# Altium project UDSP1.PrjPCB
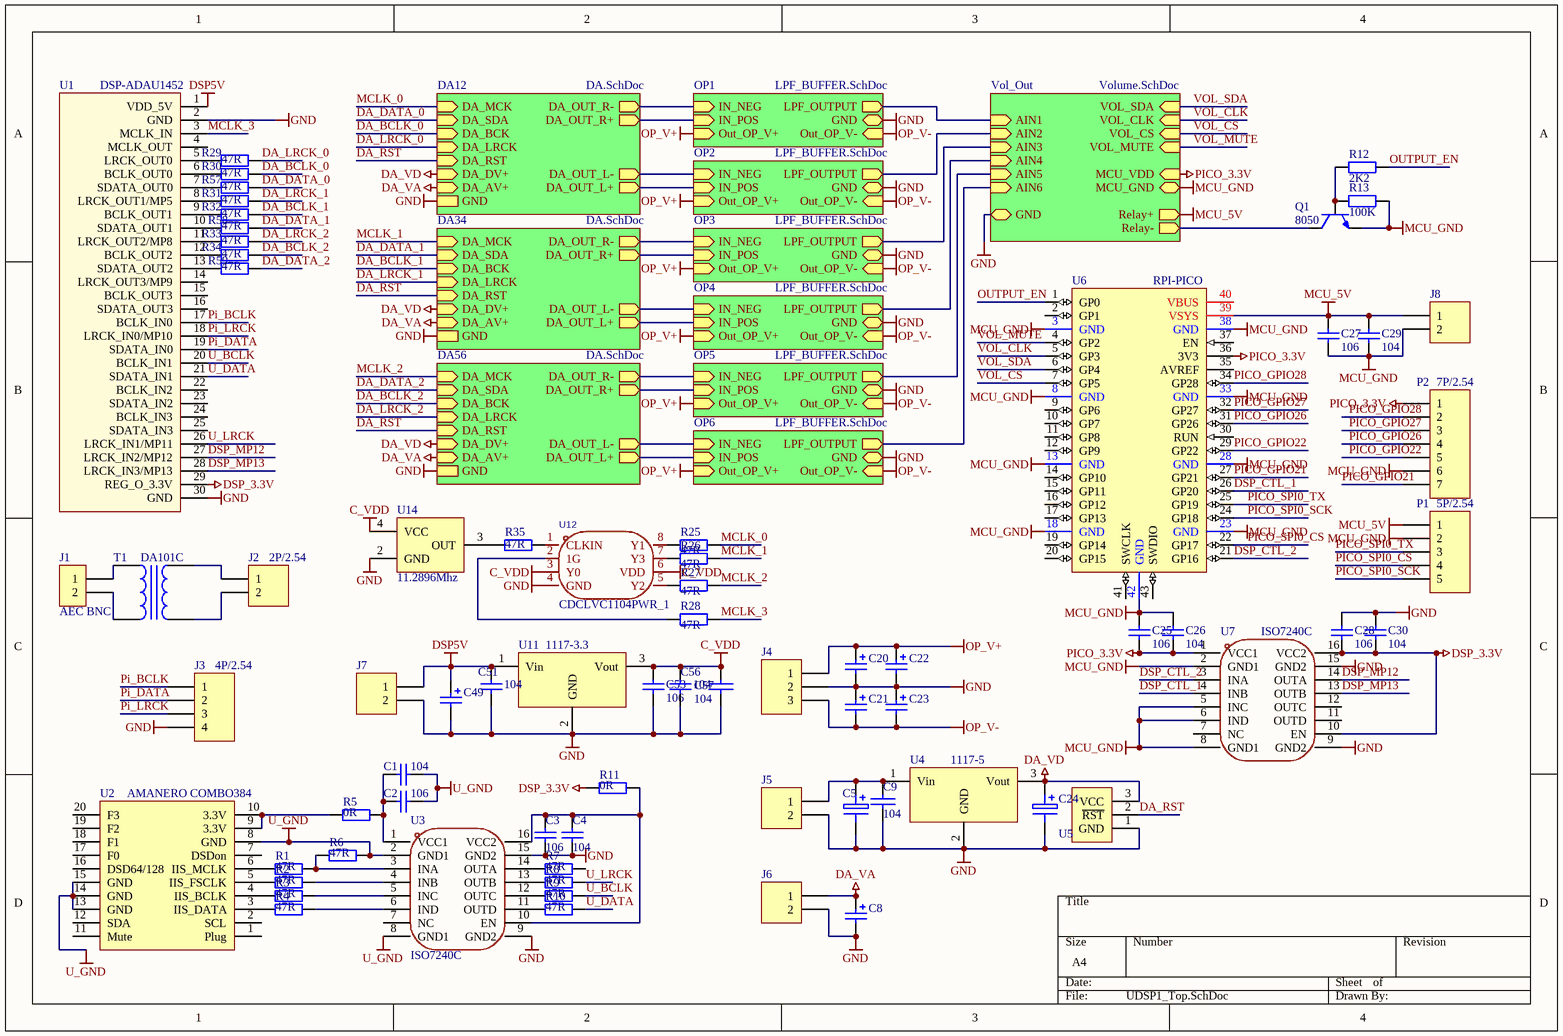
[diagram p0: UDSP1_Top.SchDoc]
4 sheets, 319 parts. Net scope: hierarchical (ports join the sheet entries above them; power ports are global).
Sheets:
  UDSP1_Top.SchDoc
    DA56 = DA.SchDoc
    Vol_Out = Volume.SchDoc
    OP1 = LPF_BUFFER.SchDoc
    OP2 = LPF_BUFFER.SchDoc
    OP3 = LPF_BUFFER.SchDoc
    OP4 = LPF_BUFFER.SchDoc
    OP5 = LPF_BUFFER.SchDoc
    OP6 = LPF_BUFFER.SchDoc
    DA34 = DA.SchDoc
    DA12 = DA.SchDoc

## Sheet UDSP1_Top.SchDoc
size A4

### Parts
C1  104  [0805]
C2  106  [c1210c]
C3  106  [c1210c]
C4  104  [0805]
C5  16V270uf OSCON  [RB.2/.4S]  (value not drawn)
C8  16V270uf OSCON  [RB.2/.4S]  (value not drawn)
C9  104  [0805]
C20  40V150uf  [PEG124_D]  (value not drawn)
C21  40V150uf  [PEG124_D]  (value not drawn)
C22  40V150uf  [PEG124_D]  (value not drawn)
C23  40V150uf  [PEG124_D]  (value not drawn)
C24  16V270uf OSCON  [RB.2/.4S]  (value not drawn)
C25  106  [c1210c]
C26  104  [0805]
C27  106  [c1210c]
C28  106  [c1210c]
C29  104  [0805]
C30  104  [0805]
C49  16V270uf OSCON  [RB.2/.4S]  (value not drawn)
C51  104  [0805]
C53  106  [C1210C]
C56  104  [0805]
C57  104  [0805]
J1  AEC BNC  [AEC_RCA_JACK]
J2  2P/2.54  [SIP2C]
J3  4P/2.54  [SIP4C]
J4  3P/2.54  [SIP3C]  (value not drawn)
J5  2P/2.54  [SIP2C]  (value not drawn)
J6  2P/2.54  [SIP2C]  (value not drawn)
J7  2P/2.54  [SIP2C]  (value not drawn)
J8  2P/2.54  [SIP2C]  (value not drawn)
P1  5P/2.54  [SIP5C]
P2  7P/2.54  [HDR1X7]
Q1  8050  [8050]
R1  47R  [0805]
R2  47R  [0805]
R3  47R  [0805]
R4  47R  [0805]
R5  0R  [0805]
R6  47R  [0805]
R7  47R  [0805]
R8  47R  [0805]
R9  47R  [0805]
R10  47R  [0805]
R11  0R  [0805]
R12  2K2  [0805]
R13  100K  [0805]
R25  47R  [0805]
R26  47R  [0805]
R27  47R  [0805]
R28  47R  [0805]
R29  47R  [0805]
R30  47R  [0805]
R31  47R  [0805]
R32  47R  [0805]
R33  47R  [0805]
R34  47R  [0805]
R35  47R  [0805]
R57  47R  [0805]
R58  47R  [0805]
R59  47R  [0805]
T1  DA101C  [PULSET]
U1  DSP-ADAU1452  [YJL1452]
U2  AMANERO COMBO384  [AMANERO_COMBO384]
U3  ISO7240C  [soic16w]
U4  1117-5  [SOT-223]
U5  IMP809R-TD 2.63V Active low  [SOT-23C]  (value not drawn)
U6  RPI-PICO  [RPI-PICO-MOD]
U7  ISO7240C  [soic16w]
U11  1117-3.3  [SOT-223]
U12  CDCLVC1104PWR_1  [tssop-8]
U14  11.2896Mhz  [OSC]

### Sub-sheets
DA12 = DA.SchDoc: DA_MCK (in), DA_SDA (in), DA_BCK (in), DA_LRCK (in), DA_RST (in), DA_OUT_R+ (out), DA_OUT_R- (out), DA_OUT_L+ (out), DA_OUT_L- (out), DA_DV+ (in), DA_AV+ (in), GND
DA34 = DA.SchDoc: DA_MCK (in), DA_SDA (in), DA_BCK (in), DA_LRCK (in), DA_RST (in), DA_OUT_R+ (out), DA_OUT_R- (out), DA_OUT_L+ (out), DA_OUT_L- (out), DA_DV+ (in), DA_AV+ (in), GND
DA56 = DA.SchDoc: DA_MCK (in), DA_SDA (in), DA_BCK (in), DA_LRCK (in), DA_RST (in), DA_OUT_R+ (out), DA_OUT_R- (out), DA_OUT_L+ (out), DA_OUT_L- (out), DA_DV+ (in), DA_AV+ (in), GND
OP1 = LPF_BUFFER.SchDoc: IN_NEG (in), IN_POS (in), Out_OP_V+, Out_OP_V-, GND, LPF_OUTPUT
OP2 = LPF_BUFFER.SchDoc: IN_NEG (in), IN_POS (in), Out_OP_V+, Out_OP_V-, GND, LPF_OUTPUT
OP3 = LPF_BUFFER.SchDoc: IN_NEG (in), IN_POS (in), Out_OP_V+, Out_OP_V-, GND, LPF_OUTPUT
OP4 = LPF_BUFFER.SchDoc: IN_NEG (in), IN_POS (in), Out_OP_V+, Out_OP_V-, GND, LPF_OUTPUT
OP5 = LPF_BUFFER.SchDoc: IN_NEG (in), IN_POS (in), Out_OP_V+, Out_OP_V-, GND, LPF_OUTPUT
OP6 = LPF_BUFFER.SchDoc: IN_NEG (in), IN_POS (in), Out_OP_V+, Out_OP_V-, GND, LPF_OUTPUT
Vol_Out = Volume.SchDoc: VOL_SDA (in), VOL_CS (in), VOL_MUTE (in), AIN1, AIN2, AIN3, AIN4, AIN6, AIN5, Relay+, Relay-, VOL_CLK (in), MCU_GND, MCU_VDD (in), GND

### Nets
C_VDD: C53.1 C56.1 C57.1 U11.3(Vout) U12.3(Y0) U12.6(VDD) U14.4(VCC)
DA_VA: C8.1 J6.1 ; sheet DA56/DA_AV+, sheet DA34/DA_AV+, sheet DA12/DA_AV+
DA_VD: C24.1 U4.3(Vout) U5.3(VCC) ; sheet DA56/DA_DV+, sheet DA34/DA_DV+, sheet DA12/DA_DV+
DSP5V: C49.1 C51.1 J7.1 U1.1(VDD_5V) U11.1(Vin)
DSP_3.3V: C28.1 C30.2 R11.2 U1.29(REG_O_3.3V) U7.10(EN) U7.16(VCC2)
GND: C3.1 C4.2 C5.2 C8.2 C9.2 C20.2 C21.1 C22.2 C23.1 C24.2 C28.2 C30.1 C49.2 C51.2 C53.2 C56.2 C57.2 J3.4 J4.2 J5.2 J6.2 J7.2 U1.2(GND) U1.30(GND) U3.9(GND2) U3.15(GND2) U4.2(GND) U5.1(GND) U7.9(GND2) U7.15(GND2) U11.2(GND) U12.4(GND) U14.2(GND) ; sheet DA56/GND, sheet Vol_Out/GND, sheet OP1/GND, sheet OP2/GND, sheet OP3/GND, sheet OP4/GND, sheet OP5/GND, sheet OP6/GND, sheet DA34/GND, sheet DA12/GND
MCU_5V: C27.2 C29.1 J8.1 P1.1 U6.39(VSYS) ; sheet Vol_Out/Relay+
MCU_GND: C25.2 C26.1 C27.1 C29.2 J8.2 P1.2 P2.6 Q1.E R13.2 U6.3(GND) U6.8(GND) U6.13(GND) U6.18(GND) U6.23(GND) U6.28(GND) U6.33(GND) U6.38(GND) U6.42(GND) U7.2(GND1) U7.5(INC) U7.6(IND) U7.8(GND1) ; sheet Vol_Out/MCU_GND
OP_V+: C20.1 C22.1 J4.1 ; sheet OP1/Out_OP_V+, sheet OP2/Out_OP_V+, sheet OP3/Out_OP_V+, sheet OP4/Out_OP_V+, sheet OP5/Out_OP_V+, sheet OP6/Out_OP_V+  [project net O_V+]
OP_V-: C21.2 C23.2 J4.3 ; sheet OP1/Out_OP_V-, sheet OP2/Out_OP_V-, sheet OP3/Out_OP_V-, sheet OP4/Out_OP_V-, sheet OP5/Out_OP_V-, sheet OP6/Out_OP_V-  [project net O_V-]
PICO_3.3V: C25.1 C26.2 P2.1 U6.36(3V3) U7.1(VCC1) ; sheet Vol_Out/MCU_VDD
Relay-: Q1.C ; sheet Vol_Out/Relay-
U_GND: C1.2 C2.1 R6.2 U2.8(GND) U2.13(GND) U2.14(GND) U2.15(GND) U3.2(GND1) U3.8(GND1)
AIN1: sheet Vol_Out/AIN1, sheet OP1/LPF_OUTPUT
AIN2: sheet Vol_Out/AIN2, sheet OP2/LPF_OUTPUT
AIN3: sheet Vol_Out/AIN3, sheet OP3/LPF_OUTPUT
AIN4: sheet Vol_Out/AIN4, sheet OP4/LPF_OUTPUT
AIN5: sheet Vol_Out/AIN5, sheet OP5/LPF_OUTPUT
AIN6: sheet Vol_Out/AIN6, sheet OP6/LPF_OUTPUT
DA_BCLK_0: R30.2 ; sheet DA12/DA_BCK
DA_BCLK_1: R32.2 ; sheet DA34/DA_BCK
DA_BCLK_2: R34.2 ; sheet DA56/DA_BCK
DA_DATA_0: R57.2 ; sheet DA12/DA_SDA
DA_DATA_1: R58.2 ; sheet DA34/DA_SDA
DA_DATA_2: R59.2 ; sheet DA56/DA_SDA
DA_LRCK_0: R29.2 ; sheet DA12/DA_LRCK
DA_LRCK_1: R31.2 ; sheet DA34/DA_LRCK
DA_LRCK_2: R33.2 ; sheet DA56/DA_LRCK
DA_RST: U5.2(~{RST}) ; sheet DA56/DA_RST, sheet DA34/DA_RST, sheet DA12/DA_RST
DSP_CTL_1: U6.26(GP20) U7.4(INB)
DSP_CTL_2: U6.21(GP16) U7.3(INA)
DSP_MP12: U1.27(LRCK_IN2/MP12) U7.14(OUTA)
DSP_MP13: U1.28(LRCK_IN3/MP13) U7.13(OUTB)
MCLK_0: R25.2 ; sheet DA12/DA_MCK
MCLK_1: R26.2 ; sheet DA34/DA_MCK
MCLK_2: R27.2 ; sheet DA56/DA_MCK
MCLK_3: R28.2 U1.3(MCLK_IN)
OUTPUT_EN: R12.1 U6.1(GP0)
Pi_BCLK: J3.1 U1.17(BCLK_IN0)
Pi_DATA: J3.2 U1.19(SDATA_IN0)
Pi_LRCK: J3.3 U1.18(LRCK_IN0/MP10)
PICO_GPIO21: P2.7 U6.27(GP21)
PICO_GPIO22: P2.5 U6.29(GP22)
PICO_GPIO26: P2.4 U6.31(GP26)
PICO_GPIO27: P2.3 U6.32(GP27)
PICO_GPIO28: P2.2 U6.34(GP28)
PICO_SPI0_CS: P1.4 U6.22(GP17)
PICO_SPI0_SCK: P1.5 U6.24(GP18)
PICO_SPI0_TX: P1.3 U6.25(GP19)
U_BCLK: R9.2 U1.20(BCLK_IN1)
U_DATA: R10.2 U1.21(SDATA_IN1)
U_LRCK: R8.2 U1.26(LRCK_IN1/MP11)
VOL_CLK: U6.5(GP3) ; sheet Vol_Out/VOL_CLK
VOL_CS: U6.7(GP5) ; sheet Vol_Out/VOL_CS
VOL_MUTE: U6.4(GP2) ; sheet Vol_Out/VOL_MUTE
VOL_SDA: U6.6(GP4) ; sheet Vol_Out/VOL_SDA
NetC1_1: C1.1 C2.2 R5.2 U3.1(VCC1)
NetC3_2: C3.2 C4.1 R11.1 U3.10(EN) U3.16(VCC2)
NetC5_1: C5.1 C9.1 J5.1 U4.1(Vin)
NetJ1_1: J1.1 T1.1
NetJ1_2: J1.2 T1.2
NetJ2_1: J2.1 T1.3
NetJ2_2: J2.2 T1.4
NetQ1_B: Q1.B R12.2 R13.1
NetR1_1: R1.1 U2.6(IIS_MCLK)
NetR1_2: R1.2 R6.1 U3.3(INA)
NetR2_1: R2.1 U2.5(IIS_FSCLK)
NetR2_2: R2.2 U3.4(INB)
NetR3_1: R3.1 U2.4(IIS_BCLK)
NetR3_2: R3.2 U3.5(INC)
NetR4_1: R4.1 U2.3(IIS_DATA)
NetR4_2: R4.2 U3.6(IND)
NetR5_1: R5.1 U2.9(3.3V) U2.10(3.3V)
NetR7_1: R7.1 U3.14(OUTA)
NetR8_1: R8.1 U3.13(OUTB)
NetR9_1: R9.1 U3.12(OUTC)
NetR10_1: R10.1 U3.11(OUTD)
NetR17A_1: sheet OP1/IN_NEG, sheet DA12/DA_OUT_R-
NetR17B_1: sheet OP2/IN_NEG, sheet DA12/DA_OUT_L-
NetR17C_1: sheet OP3/IN_NEG, sheet DA34/DA_OUT_R-
NetR17D_1: sheet OP4/IN_NEG, sheet DA34/DA_OUT_L-
NetR17E_1: sheet DA56/DA_OUT_R-, sheet OP5/IN_NEG
NetR17F_1: sheet DA56/DA_OUT_L-, sheet OP6/IN_NEG
NetR18A_1: sheet OP1/IN_POS, sheet DA12/DA_OUT_R+
NetR18B_1: sheet OP2/IN_POS, sheet DA12/DA_OUT_L+
NetR18C_1: sheet OP3/IN_POS, sheet DA34/DA_OUT_R+
NetR18D_1: sheet OP4/IN_POS, sheet DA34/DA_OUT_L+
NetR18E_1: sheet DA56/DA_OUT_R+, sheet OP5/IN_POS
NetR18F_1: sheet DA56/DA_OUT_L+, sheet OP6/IN_POS
NetR25_1: R25.1 U12.8(Y1)
NetR26_1: R26.1 U12.7(Y3)
NetR27_1: R27.1 U12.5(Y2)
NetR28_1: R28.1 U12.2(1G)
NetR29_1: R29.1 U1.5(LRCK_OUT0)
NetR30_1: R30.1 U1.6(BCLK_OUT0)
NetR31_1: R31.1 U1.8(LRCK_OUT1/MP5)
NetR32_1: R32.1 U1.9(BCLK_OUT1)
NetR33_1: R33.1 U1.11(LRCK_OUT2/MP8)
NetR34_1: R34.1 U1.12(BCLK_OUT2)
NetR35_1: R35.1 U14.3(OUT)
NetR35_2: R35.2 U12.1(CLKIN)
NetR57_1: R57.1 U1.7(SDATA_OUT0)
NetR58_1: R58.1 U1.10(SDATA_OUT1)
NetR59_1: R59.1 U1.13(SDATA_OUT2)

Not connected (* = marked no-connect by the designer): R7 2; U1 4(MCLK_OUT) 14(LRCK_OUT3/MP9) 15(BCLK_OUT3) 16(SDATA_OUT3) 22(BCLK_IN2) 23(SDATA_IN2) 24(BCLK_IN3) 25(SDATA_IN3); U2 1(Plug) 2(SCL) 7(DSDon) 11(Mute) 12(SDA) 16(DSD64/128) 17(F0) 18(F1) 19(F2) 20(F3); U3 7(NC); U6 2(GP1) 9(GP6) 10(GP7) 11(GP8) 12(GP9) 14(GP10) 15(GP11) 16(GP12) 17(GP13) 19(GP14) 20(GP15) 30(RUN) 35(AVREF) 37(EN) 40(VBUS) 41(SWCLK) 43(SWDIO); U7 7(NC) 11(OUTD) 12(OUTC)

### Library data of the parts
C1-C4 C25-C30 C51 C56 = Cap: Capacitor; Value: 100pF
C5 C24 = ELECTRO1: Electrolytic Capacitor
C8 C20-C23 C49 = Cap Pol2: Polarized Capacitor (Axial); Value: 100pF
C9 C53 C57 = CAP: Capacitor
J1 = CON2: Connector
J2 J5-J8 = Header 2: Header, 2-Pin
J3 = Header 4: Header, 4-Pin
J4 = Header 3: Header, 3-Pin
P1 = Header 5: Header, 5-Pin
P2 = Header 7: Header, 7-Pin
Q1 = NPNTR
R1-R13 R25-R35 R57-R59 = Res2: Resistor; Value: 1K
T1 = TRANS1
U1 = YJL1452
U3 U7 = ISO7240
U4 U11 = VOLTREG: pin to pad: 1>3 2>1 3>2
U5 = IMP709: pin to pad: 1>B 2>E 3>C
U6 = RPI-PICO-MOD_SM: RASPBERRY PI PICO RP2040 BOARD NO TEST PADS; Manufacturer: Raspberry Pi Foundation; Manufacturer Part No: SC0915
U14 = OSC

## Sheet DA.SchDoc
size A4
Used 3 times, as channels DA56, DA34, DA12. Parts and nets are listed once, with the designators drawn on the sheet.
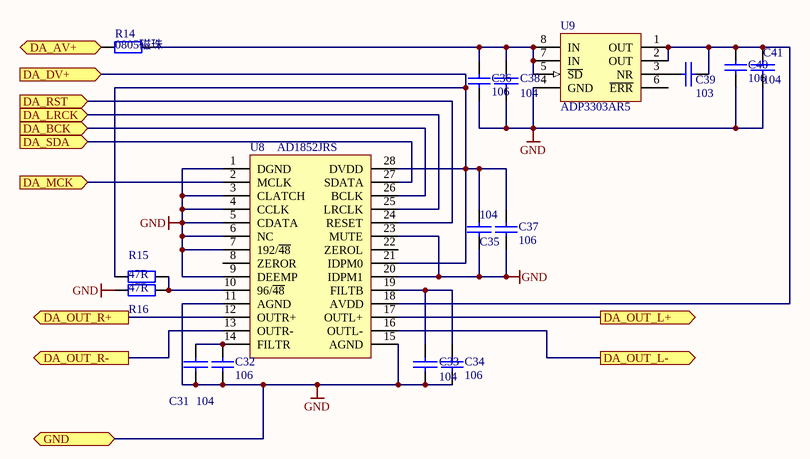
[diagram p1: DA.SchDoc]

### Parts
C31  104  [0805]
C32  106  [C1210C]
C33  104  [0805]
C34  106  [C1210C]
C35  104  [0805]
C36  106  [C1210C]
C37  106  [c1210C]
C38  104  [0805]
C39  103  [0805]
C40  106  [C1210C]
C41  104  [0805]
R14  0805磁珠  [0805]
R15  47R  [0805]
R16  47R  [0805]
U8  AD1852JRS  [SSOP28]
U9  ADP3303AR5  [SOP8]

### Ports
DA_AV+ (in), DA_BCK (in), DA_DV+ (in), DA_LRCK (in), DA_MCK (in), DA_OUT_L+ (out), DA_OUT_L- (out), DA_OUT_R+ (out), DA_OUT_R- (out), DA_RST (in), DA_SDA (in), GND

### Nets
GND: C31.2 C32.2 C33.2 C34.2 C35.2 C36.2 C37.2 C38.2 C40.2 C41.2 R16.2 U8.1(DGND) U8.3(CLATCH) U8.4(CCLK) U8.5(CDATA) U8.6(NC) U8.7(192/~{48}) U8.9(DEEMP) U8.11(AGND) U8.15(AGND) U8.20(IDPM1) U8.23(MUTE) U9.4(GND) ; port GND
DA_AV+: R14.2 ; port DA_AV+
DA_BCK: U8.26(BCLK) ; port DA_BCK
DA_DV+: C35.1 C37.1 R15.2 U8.21(IDPM0) U8.28(DVDD) ; port DA_DV+
DA_LRCK: U8.25(LRCLK) ; port DA_LRCK
DA_MCK: U8.2(MCLK) ; port DA_MCK
DA_OUT_L+: U8.17(OUTL+) ; port DA_OUT_L+
DA_OUT_L-: U8.16(OUTL-) ; port DA_OUT_L-
DA_OUT_R+: U8.12(OUTR+) ; port DA_OUT_R+
DA_OUT_R-: U8.13(OUTR-) ; port DA_OUT_R-
DA_RST: U8.24(RESET) ; port DA_RST
DA_SDA: U8.27(SDATA) ; port DA_SDA
NetC31_1: C31.1 C32.1 U8.14(FILTR)
NetC33_1: C33.1 C34.1 U8.19(FILTB)
NetC36_1: C36.1 C38.1 R14.1 U9.5(~{SD}) U9.7(IN) U9.8(IN)
NetC39_1: C39.1 U9.3(NR)
NetC39_2: C39.2 C40.1 C41.1 U8.18(AVDD) U9.1(OUT) U9.2(OUT)
NetR15_1: R15.1 R16.1 U8.10(96/~{48})

Not connected (* = marked no-connect by the designer): U8 8(ZEROR) 22(ZEROL); U9 6(~{ERR})

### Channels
DA56: designators end in A; ports DA_AV+=DA_VA DA_BCK=DA_BCLK_2 DA_DV+=DA_VD DA_LRCK=DA_LRCK_2 DA_MCK=MCLK_2 DA_OUT_L+=NetR18F_1 DA_OUT_L-=NetR17F_1 DA_OUT_R+=NetR18E_1 DA_OUT_R-=NetR17E_1 DA_RST=DA_RST DA_SDA=DA_DATA_2 GND=GND
DA34: designators end in B; ports DA_AV+=DA_VA DA_BCK=DA_BCLK_1 DA_DV+=DA_VD DA_LRCK=DA_LRCK_1 DA_MCK=MCLK_1 DA_OUT_L+=NetR18D_1 DA_OUT_L-=NetR17D_1 DA_OUT_R+=NetR18C_1 DA_OUT_R-=NetR17C_1 DA_RST=DA_RST DA_SDA=DA_DATA_1 GND=GND
DA12: designators end in C; ports DA_AV+=DA_VA DA_BCK=DA_BCLK_0 DA_DV+=DA_VD DA_LRCK=DA_LRCK_0 DA_MCK=MCLK_0 DA_OUT_L+=NetR18B_1 DA_OUT_L-=NetR17B_1 DA_OUT_R+=NetR18A_1 DA_OUT_R-=NetR17A_1 DA_RST=DA_RST DA_SDA=DA_DATA_0 GND=GND

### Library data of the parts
C31 C33 C35 C38-C41 = CAP: Capacitor
C32 C34 C36 = CAP: Capacitor; Value: 100pF
C37 = Cap: Capacitor; Value: 100pF
R14-R16 = Res2: Resistor; Value: 1K
U8 = AD1852
U9 = ADP3303AR5: High-Accuracy anyCAP 200mA Low-Dropout Linear Regulator; PackageDocument: revA; Note: Pins 1 & 2 and pins 7 & 8 must be connected together for proper operation

## Sheet Volume.SchDoc
size A4
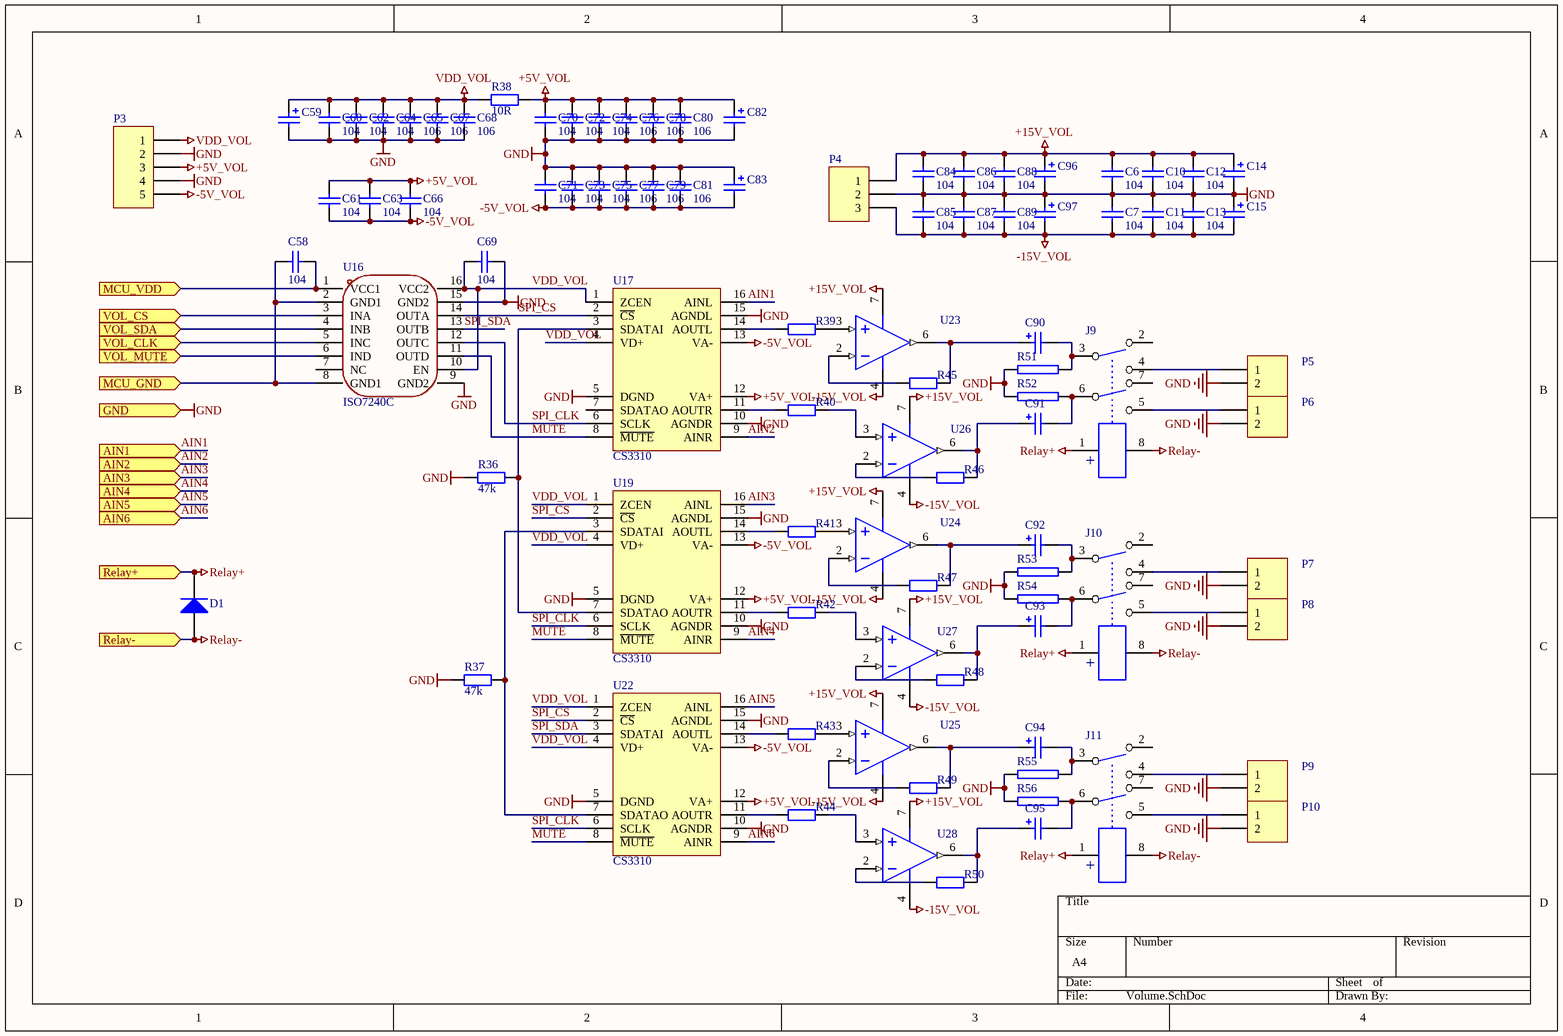
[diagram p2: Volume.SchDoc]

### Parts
C6  104  [0805]
C7  104  [0805]
C10  104  [0805]
C11  104  [0805]
C12  104  [0805]
C13  104  [0805]
C14  40V150uf  [PEG124_D]  (value not drawn)
C15  40V150uf  [PEG124_D]  (value not drawn)
C58  104  [0805]
C59  16V270uf OSCON  [RB.2/.4S]  (value not drawn)
C60  104  [0805]
C61  104  [0805]
C62  104  [0805]
C63  104  [0805]
C64  104  [0805]
C65  106  [C1210C]
C66  104  [0805]
C67  106  [C1210C]
C68  106  [C1210C]
C69  104  [0805]
C70  104  [0805]
C71  104  [0805]
C72  104  [0805]
C73  104  [0805]
C74  104  [0805]
C75  104  [0805]
C76  106  [C1210C]
C77  106  [C1210C]
C78  106  [C1210C]
C79  106  [C1210C]
C80  106  [C1210C]
C81  106  [C1210C]
C82  16V270uf OSCON  [RB.2/.4S]  (value not drawn)
C83  16V270uf OSCON  [RB.2/.4S]  (value not drawn)
C84  104  [0805]
C85  104  [0805]
C86  104  [0805]
C87  104  [0805]
C88  104  [0805]
C89  104  [0805]
C90  47uF 25V BP  [RB.2/.4S]  (value not drawn)
C91  47uF 25V BP  [RB.2/.4S]  (value not drawn)
C92  47uF 25V BP  [RB.2/.4S]  (value not drawn)
C93  47uF 25V BP  [RB.2/.4S]  (value not drawn)
C94  47uF 25V BP  [RB.2/.4S]  (value not drawn)
C95  47uF 25V BP  [RB.2/.4S]  (value not drawn)
C96  40V150uf  [PEG124_D]  (value not drawn)
C97  40V150uf  [PEG124_D]  (value not drawn)
D1  1N4007 M7 SMA  [smd_4007]  (value not drawn)
J9  TXD2SA-5V  [Relay_TXD2SA]  (value not drawn)
J10  TXD2SA-5V  [Relay_TXD2SA]  (value not drawn)
J11  TXD2SA-5V  [Relay_TXD2SA]  (value not drawn)
P3  5P/2.54  [SIP5C]  (value not drawn)
P4  3P/2.54  [SIP3C]  (value not drawn)
P5  2P/2.54  [sip2c]  (value not drawn)
P6  2P/2.54  [sip2c]  (value not drawn)
P7  2P/2.54  [sip2c]  (value not drawn)
P8  2P/2.54  [sip2c]  (value not drawn)
P9  2P/2.54  [sip2c]  (value not drawn)
P10  2P/2.54  [sip2c]  (value not drawn)
R36  47k  [0805]
R37  47k  [0805]
R38  10R  [0805]
R39  200R  [0805]  (value not drawn)
R40  200R  [0805]  (value not drawn)
R41  200R  [0805]  (value not drawn)
R42  200R  [0805]  (value not drawn)
R43  200R  [0805]  (value not drawn)
R44  200R  [0805]  (value not drawn)
R45  200R  [0805]  (value not drawn)
R46  200R  [0805]  (value not drawn)
R47  200R  [0805]  (value not drawn)
R48  200R  [0805]  (value not drawn)
R49  200R  [0805]  (value not drawn)
R50  200R  [0805]  (value not drawn)
R51  10K  [0805]  (value not drawn)
R52  10K  [0805]  (value not drawn)
R53  10K  [0805]  (value not drawn)
R54  10K  [0805]  (value not drawn)
R55  10K  [0805]  (value not drawn)
R56  10K  [0805]  (value not drawn)
U16  ISO7240C  [soic16w]
U17  CS3310  [DIP16]
U19  CS3310  [DIP16]
U22  CS3310  [DIP16]
U23  NE5534  [DIP8]  (value not drawn)
U24  NE5534  [DIP8]  (value not drawn)
U25  NE5534  [DIP8]  (value not drawn)
U26  NE5534  [DIP8]  (value not drawn)
U27  NE5534  [DIP8]  (value not drawn)
U28  NE5534  [DIP8]  (value not drawn)

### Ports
AIN1, AIN2, AIN3, AIN4, AIN5, AIN6, GND, MCU_GND, MCU_VDD (in), Relay+, Relay-, VOL_CLK, VOL_CS, VOL_MUTE, VOL_SDA

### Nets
+5V_VOL: C61.2 C63.2 C66.2 C70.2 C72.2 C74.2 C76.1 C78.1 C80.1 C82.1 P3.3 R38.2 U17.12(VA+) U19.12(VA+) U22.12(VA+)
+15V_VOL: C6.2 C10.2 C12.2 C14.1 C84.2 C86.2 C88.2 C96.1 P4.1 U23.7(VCC+) U24.7(VCC+) U25.7(VCC+) U26.7(VCC+) U27.7(VCC+) U28.7(VCC+)
-5V_VOL: C61.1 C63.1 C66.1 C71.1 C73.1 C75.1 C77.2 C79.2 C81.2 C83.2 P3.5 U17.13(VA-) U19.13(VA-) U22.13(VA-)
-15V_VOL: C7.1 C11.1 C13.1 C15.2 C85.1 C87.1 C89.1 C97.2 P4.3 U23.4(VCC_-) U24.4(VCC_-) U25.4(VCC_-) U26.4(VCC_-) U27.4(VCC_-) U28.4(VCC_-)
GND: C6.1 C7.2 C10.1 C11.2 C12.1 C13.2 C14.2 C15.1 C59.2 C60.1 C62.1 C64.1 C65.2 C67.2 C68.2 C69.1 C70.1 C71.2 C72.1 C73.2 C74.1 C75.2 C76.2 C77.1 C78.2 C79.1 C80.2 C81.1 C82.2 C83.1 C84.1 C85.2 C86.1 C87.2 C88.1 C89.2 C96.2 C97.1 P3.2 P3.4 P4.2 P5.2 P6.2 P7.2 P8.2 P9.2 P10.2 R36.1 R37.1 R51.2 R52.2 R53.2 R54.2 R55.2 R56.2 U16.9(GND2) U16.15(GND2) U17.5(DGND) U17.10(AGNDR) U17.15(AGNDL) U19.5(DGND) U19.10(AGNDR) U19.15(AGNDL) U22.5(DGND) U22.10(AGNDR) U22.15(AGNDL) ; port GND
MCU_GND: C58.2 U16.2(GND1) U16.8(GND1) ; port MCU_GND
PICO_3.3V: C58.1 U16.1(VCC1) ; port MCU_VDD
Relay+: D1.2(K) J9.1 J10.1 J11.1 ; port Relay+  [project net MCU_5V]
Relay-: D1.1(A) J9.8 J10.8 J11.8 ; port Relay-
VDD_VOL: C59.1 C60.2 C62.2 C64.2 C65.1 C67.1 C68.1 C69.2 P3.1 R38.1 U16.10(EN) U16.16(VCC2) U17.1(ZCEN) U17.4(VD+) U19.1(ZCEN) U19.4(VD+) U22.1(ZCEN) U22.4(VD+)
AIN1: U17.16(AINL) ; port AIN1
AIN2: U17.9(AINR) ; port AIN2
AIN3: U19.16(AINL) ; port AIN3
AIN4: U19.9(AINR) ; port AIN4
AIN5: U22.16(AINL) ; port AIN5
AIN6: U22.9(AINR) ; port AIN6
MUTE: U16.11(OUTD) U17.8(~{MUTE}) U19.8(~{MUTE}) U22.8(~{MUTE})
SPI_CLK: U16.12(OUTC) U17.6(SCLK) U19.6(SCLK) U22.6(SCLK)
SPI_CS: U16.14(OUTA) U17.2(~{CS}) U19.2(~{CS}) U22.2(~{CS})
SPI_SDA: U16.13(OUTB) U22.3(SDATAI)
VOL_CLK: U16.5(INC) ; port VOL_CLK
VOL_CS: U16.3(INA) ; port VOL_CS
VOL_MUTE: U16.6(IND) ; port VOL_MUTE
VOL_SDA: U16.4(INB) ; port VOL_SDA
NetC90_1: C90.1 R45.2 U23.6(OUT)
NetC90_2: C90.2 J9.3 R51.1
NetC91_1: C91.1 R46.2 U26.6(OUT)
NetC91_2: C91.2 J9.6 R52.1
NetC92_1: C92.1 R47.2 U24.6(OUT)
NetC92_2: C92.2 J10.3 R53.1
NetC93_1: C93.1 R48.2 U27.6(OUT)
NetC93_2: C93.2 J10.6 R54.1
NetC94_1: C94.1 R49.2 U25.6(OUT)
NetC94_2: C94.2 J11.3 R55.1
NetC95_1: C95.1 R50.2 U28.6(OUT)
NetC95_2: C95.2 J11.6 R56.1
NetJ9_4: J9.4 P5.1
NetJ9_5: J9.5 P6.1
NetJ10_4: J10.4 P7.1
NetJ10_5: J10.5 P8.1
NetJ11_4: J11.4 P9.1
NetJ11_5: J11.5 P10.1
NetR36_2: R36.2 U17.3(SDATAI) U19.7(SDATAO)
NetR37_2: R37.2 U19.3(SDATAI) U22.7(SDATAO)
NetR39_1: R39.1 U17.14(AOUTL)
NetR39_2: R39.2 U23.3(IN+)
NetR40_1: R40.1 U17.11(AOUTR)
NetR40_2: R40.2 U26.3(IN+)
NetR41_1: R41.1 U19.14(AOUTL)
NetR41_2: R41.2 U24.3(IN+)
NetR42_1: R42.1 U19.11(AOUTR)
NetR42_2: R42.2 U27.3(IN+)
NetR43_1: R43.1 U22.14(AOUTL)
NetR43_2: R43.2 U25.3(IN+)
NetR44_1: R44.1 U22.11(AOUTR)
NetR44_2: R44.2 U28.3(IN+)
NetR45_1: R45.1 U23.2(IN-)
NetR46_1: R46.1 U26.2(IN-)
NetR47_1: R47.1 U24.2(IN-)
NetR48_1: R48.1 U27.2(IN-)
NetR49_1: R49.1 U25.2(IN-)
NetR50_1: R50.1 U28.2(IN-)

Not connected (* = marked no-connect by the designer): J9 2 7; J10 2 7; J11 2 7; U16 7(NC); U17 7(SDATAO)

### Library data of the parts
C6 C7 C10-C13 C58 C60-C64 C66 C69-C75 C84-C89 = Cap: Capacitor; Value: 100pF
C14 C15 C59 C82 C83 C90-C97 = Cap Pol2: as C8 on sheet UDSP1_Top
C65 C67 C68 C76-C81 = CAP: Capacitor
D1 = Diode: 1N4007  SMA
J9-J11 = RELAY_DPDT: NEC EC2-5NU DPDT RELAY 5V
P3 = Header 5: Header, 5-Pin
P4 = Header 3: Header, 3-Pin
P5-P10 = Header 2: Header, 2-Pin
R36-R50 = Res2: Resistor; Value: 1K
R51-R56 = RES2
U16 = ISO7240
U23-U28 = single_op

## Sheet LPF_BUFFER.SchDoc
size A4
Used 6 times, as channels OP1, OP2, OP3, OP4, OP5, OP6. Parts and nets are listed once, with the designators drawn on the sheet.
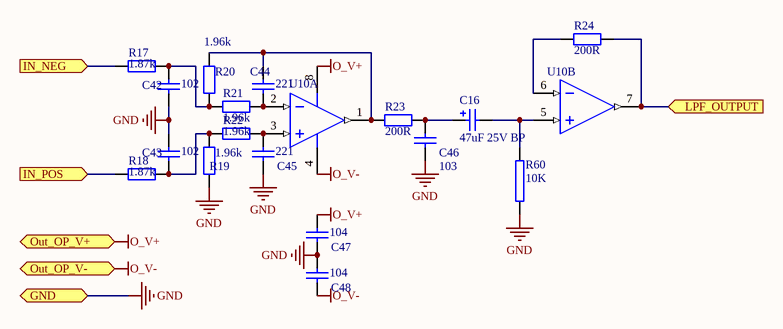
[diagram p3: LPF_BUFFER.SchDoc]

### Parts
C16  47uF 25V BP  [RB.2/.4S]
C42  102  [0805]
C43  102  [0805]
C44  221  [0805]
C45  221  [0805]
C46  103  [0805]
C47  104  [0805]
C48  104  [0805]
R17  1.87k  [0805]
R18  1.87k  [0805]
R19  1.96k  [0805]
R20  1.96k  [0805]
R21  1.96k  [0805]
R22  1.96k  [0805]
R23  200R  [0805]
R24  200R  [0805]
R60  10K  [0805]
U10  NE5532  [DIP8]  (value not drawn)  (parts A,B of 2)

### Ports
GND, IN_NEG (in), IN_POS (in), LPF_OUTPUT, Out_OP_V+, Out_OP_V-

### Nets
GND: C42.1 C43.2 C45.1 C46.1 C47.1 C48.2 R19.1 R60.2 ; port GND
O_V+: C47.2 U10.8(VCC+) ; port Out_OP_V+
O_V-: C48.1 U10.4(VCC_-) ; port Out_OP_V-
IN_NEG: R17.1 ; port IN_NEG
IN_POS: R18.1 ; port IN_POS
LPF_OUTPUT: R24.2 U10.7(OUT) ; port LPF_OUTPUT
NetC16_1: C16.1 C46.2 R23.2
NetC16_2: C16.2 R60.1 U10.5(IN+)
NetC42_2: C42.2 R17.2 R20.1 R21.1
NetC43_1: C43.1 R18.2 R19.2 R22.2
NetC44_1: C44.1 R21.2 U10.2(IN-)
NetC44_2: C44.2 R20.2 R23.1 U10.1(OUT)
NetC45_2: C45.2 R22.1 U10.3(IN+)
NetR24_1: R24.1 U10.6(IN-)

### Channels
OP1: designators end in A; ports GND=GND IN_NEG=NetR17A_1 IN_POS=NetR18A_1 LPF_OUTPUT=AIN1 Out_OP_V+=O_V+ Out_OP_V-=O_V-
OP2: designators end in B; ports GND=GND IN_NEG=NetR17B_1 IN_POS=NetR18B_1 LPF_OUTPUT=AIN2 Out_OP_V+=O_V+ Out_OP_V-=O_V-
OP3: designators end in C; ports GND=GND IN_NEG=NetR17C_1 IN_POS=NetR18C_1 LPF_OUTPUT=AIN3 Out_OP_V+=O_V+ Out_OP_V-=O_V-
OP4: designators end in D; ports GND=GND IN_NEG=NetR17D_1 IN_POS=NetR18D_1 LPF_OUTPUT=AIN4 Out_OP_V+=O_V+ Out_OP_V-=O_V-
OP5: designators end in E; ports GND=GND IN_NEG=NetR17E_1 IN_POS=NetR18E_1 LPF_OUTPUT=AIN5 Out_OP_V+=O_V+ Out_OP_V-=O_V-
OP6: designators end in F; ports GND=GND IN_NEG=NetR17F_1 IN_POS=NetR18F_1 LPF_OUTPUT=AIN6 Out_OP_V+=O_V+ Out_OP_V-=O_V-

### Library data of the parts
C16 = Cap Pol2: as C8 on sheet UDSP1_Top
C42-C48 = cap: Capacitor; Value: 100pF
R17-R24 = Res2: Resistor; Value: 1K
R60 = RES2
U10 = DUAL_OP

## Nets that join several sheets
DA_VA: UDSP1_Top (C8.1 J6.1), DA56 (R14A.2), DA34 (R14B.2), DA12 (R14C.2)
DA_VD: UDSP1_Top (C24.1 U4.3 U5.3), DA56 (5 pins), DA34 (5 pins), DA12 (5 pins)
GND: UDSP1_Top (33 pins), DA56 (23 pins), Volume (66 pins), OP1 (8 pins), OP2 (8 pins), OP3 (8 pins), OP4 (8 pins), OP5 (8 pins), OP6 (8 pins), DA34 (23 pins), DA12 (23 pins)
MCU_5V: UDSP1_Top (5 pins), Volume (D1.2 J9.1 J10.1 J11.1)
MCU_GND: UDSP1_Top (22 pins), Volume (C58.2 U16.2 U16.8)
O_V+: UDSP1_Top (C20.1 C22.1 J4.1), OP1 (C47A.2 U10A.8), OP2 (C47B.2 U10B.8), OP3 (C47C.2 U10C.8), OP4 (C47D.2 U10D.8), OP5 (C47E.2 U10E.8), OP6 (C47F.2 U10F.8)
O_V-: UDSP1_Top (C21.2 C23.2 J4.3), OP1 (C48A.1 U10A.4), OP2 (C48B.1 U10B.4), OP3 (C48C.1 U10C.4), OP4 (C48D.1 U10D.4), OP5 (C48E.1 U10E.4), OP6 (C48F.1 U10F.4)
PICO_3.3V: UDSP1_Top (5 pins), Volume (C58.1 U16.1)
Relay-: UDSP1_Top (Q1.C), Volume (D1.1 J9.8 J10.8 J11.8)
AIN1: Volume (U17.16), OP1 (R24A.2 U10A.7)
AIN2: Volume (U17.9), OP2 (R24B.2 U10B.7)
AIN3: Volume (U19.16), OP3 (R24C.2 U10C.7)
AIN4: Volume (U19.9), OP4 (R24D.2 U10D.7)
AIN5: Volume (U22.16), OP5 (R24E.2 U10E.7)
AIN6: Volume (U22.9), OP6 (R24F.2 U10F.7)
DA_BCLK_0: UDSP1_Top (R30.2), DA12 (U8C.26)
DA_BCLK_1: UDSP1_Top (R32.2), DA34 (U8B.26)
DA_BCLK_2: UDSP1_Top (R34.2), DA56 (U8A.26)
DA_DATA_0: UDSP1_Top (R57.2), DA12 (U8C.27)
DA_DATA_1: UDSP1_Top (R58.2), DA34 (U8B.27)
DA_DATA_2: UDSP1_Top (R59.2), DA56 (U8A.27)
DA_LRCK_0: UDSP1_Top (R29.2), DA12 (U8C.25)
DA_LRCK_1: UDSP1_Top (R31.2), DA34 (U8B.25)
DA_LRCK_2: UDSP1_Top (R33.2), DA56 (U8A.25)
DA_RST: UDSP1_Top (U5.2), DA56 (U8A.24), DA34 (U8B.24), DA12 (U8C.24)
MCLK_0: UDSP1_Top (R25.2), DA12 (U8C.2)
MCLK_1: UDSP1_Top (R26.2), DA34 (U8B.2)
MCLK_2: UDSP1_Top (R27.2), DA56 (U8A.2)
NetR17A_1: OP1 (R17A.1), DA12 (U8C.13)
NetR17B_1: OP2 (R17B.1), DA12 (U8C.16)
NetR17C_1: OP3 (R17C.1), DA34 (U8B.13)
NetR17D_1: OP4 (R17D.1), DA34 (U8B.16)
NetR17E_1: DA56 (U8A.13), OP5 (R17E.1)
NetR17F_1: DA56 (U8A.16), OP6 (R17F.1)
NetR18A_1: OP1 (R18A.1), DA12 (U8C.12)
NetR18B_1: OP2 (R18B.1), DA12 (U8C.17)
NetR18C_1: OP3 (R18C.1), DA34 (U8B.12)
NetR18D_1: OP4 (R18D.1), DA34 (U8B.17)
NetR18E_1: DA56 (U8A.12), OP5 (R18E.1)
NetR18F_1: DA56 (U8A.17), OP6 (R18F.1)
VOL_CLK: UDSP1_Top (U6.5), Volume (U16.5)
VOL_CS: UDSP1_Top (U6.7), Volume (U16.3)
VOL_MUTE: UDSP1_Top (U6.4), Volume (U16.6)
VOL_SDA: UDSP1_Top (U6.6), Volume (U16.4)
